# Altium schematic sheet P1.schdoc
size 594 x 419 mm; Symbol: Drawing-Symbol_A4; Company: 嘉立创EDA; Version: V1.0; Page Size: A4; @Project Name: 2026-07-10_18-27-02-有刷私服2; @Update Date: 2026-07-10; @Create Date: 2026-07-10; Device: Drawing-Symbol_A4; @Board Name: Board1; @Page Name: P1; @Create Time: 18:27:26; @Page Count: 1; @Page No: 1; @Schematic Name: Schematic1; @Update Time: 18:27:26; @Assembly Variant: Basic; Border: 1; Title Block Position: 3; Size: A4; Width: 2338; Height: 1652; Region Start: 1; X Region Count: 6; Y Region Count: 4; Blade Width: 10
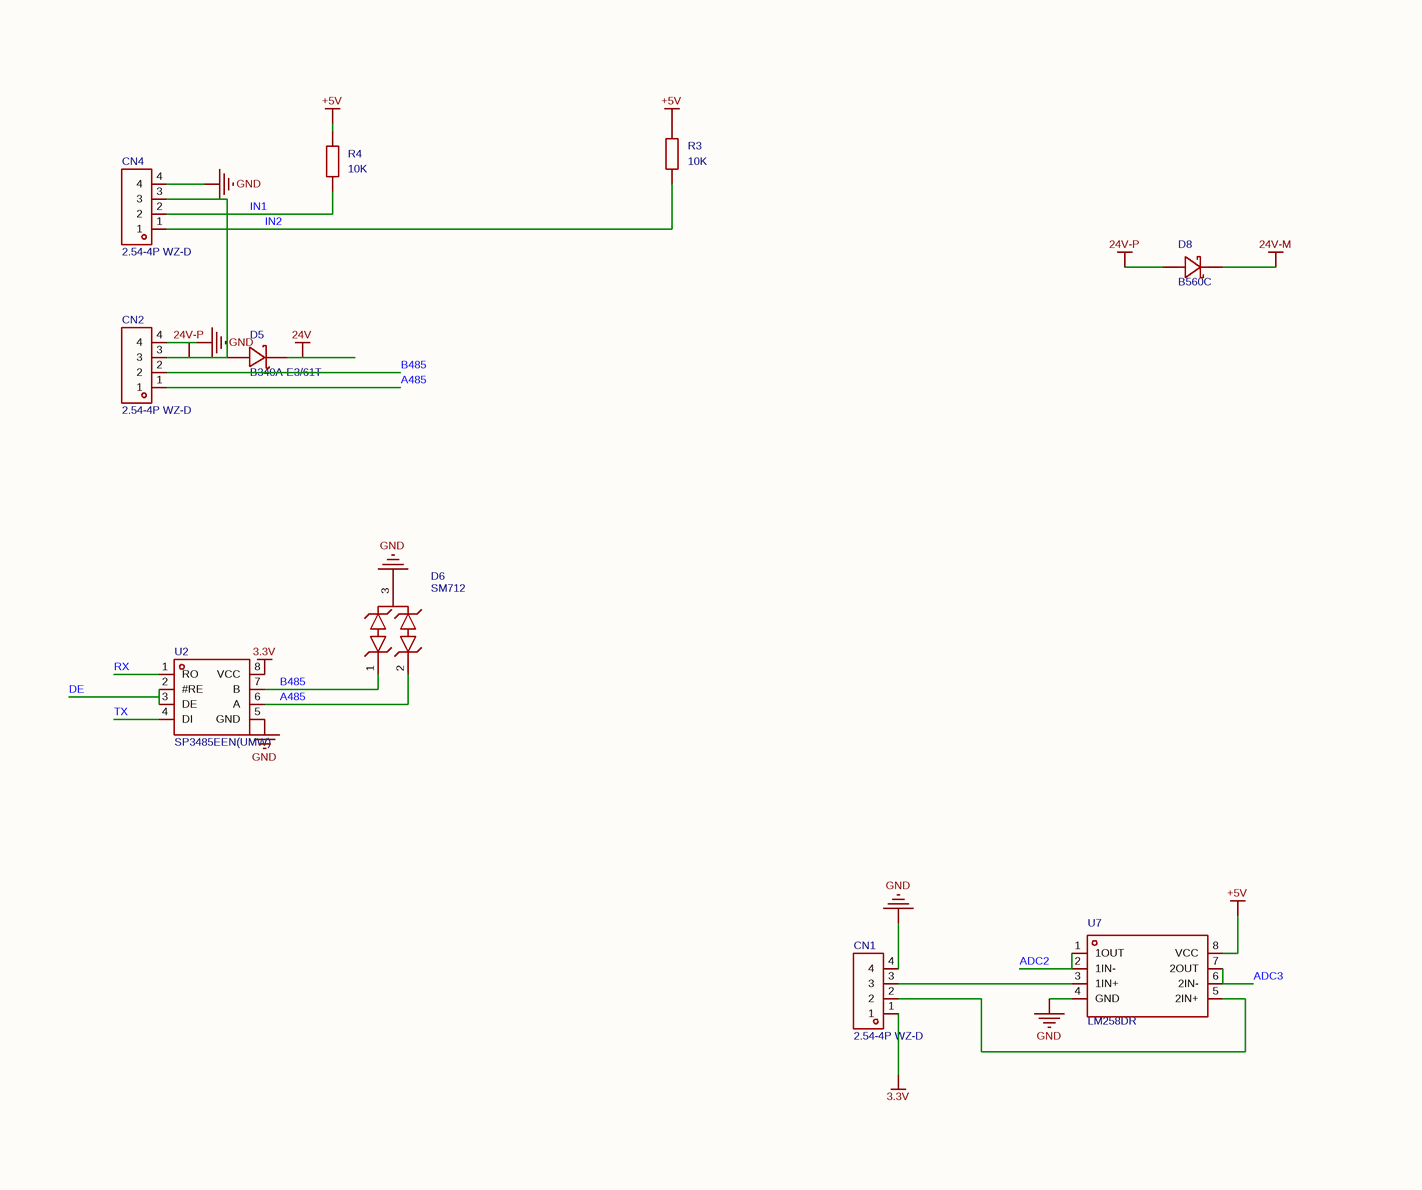
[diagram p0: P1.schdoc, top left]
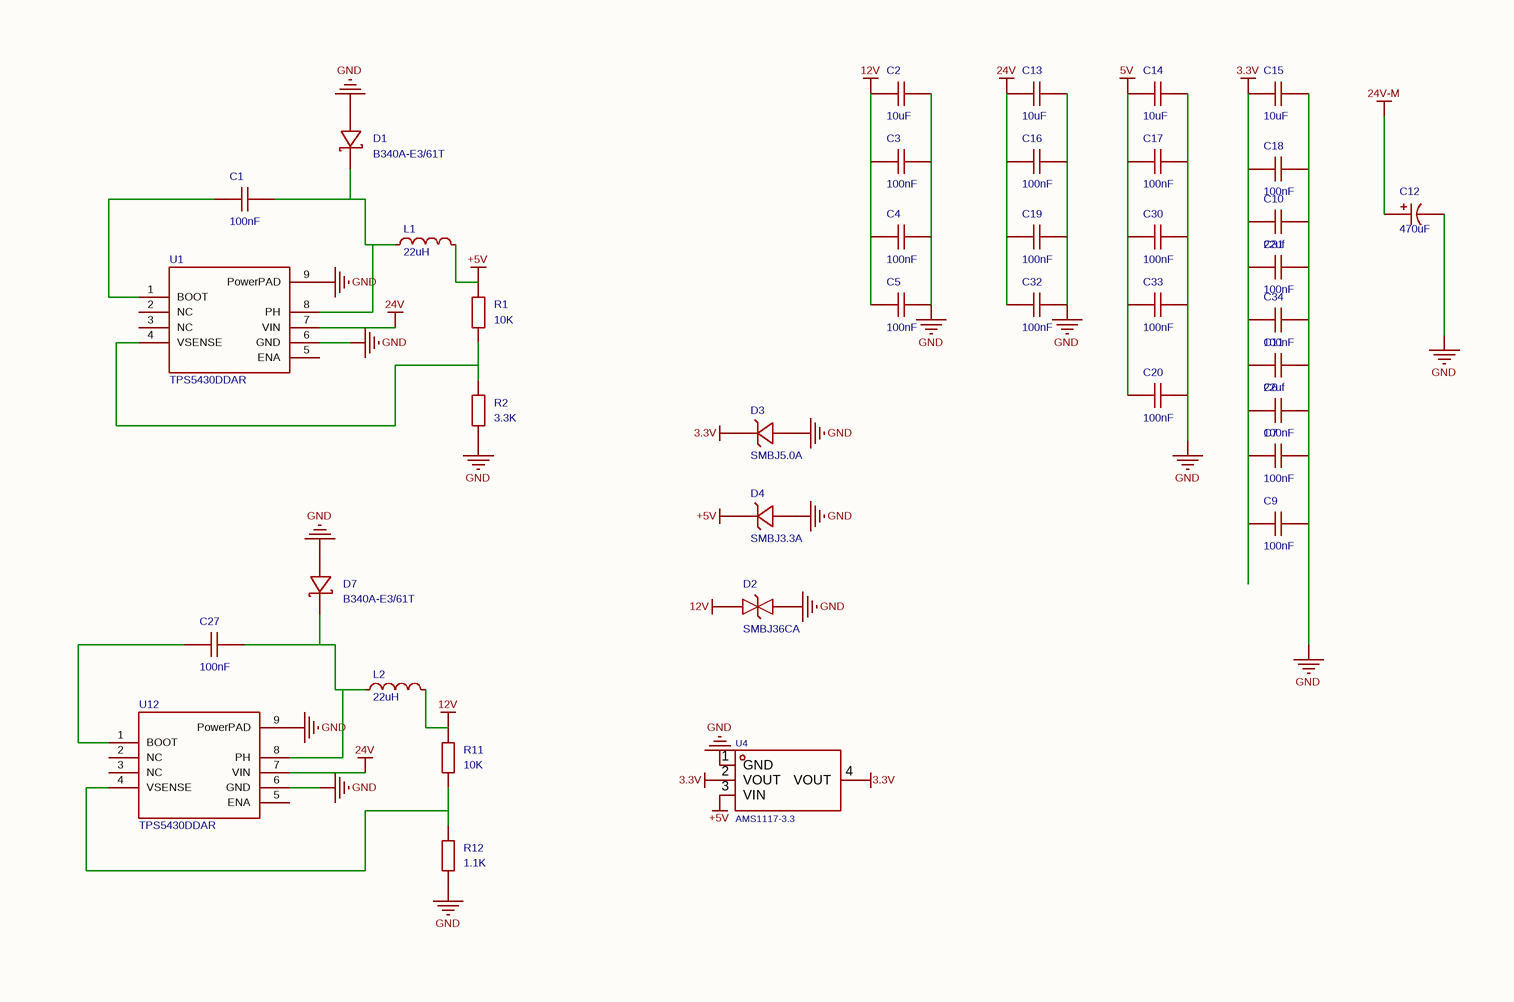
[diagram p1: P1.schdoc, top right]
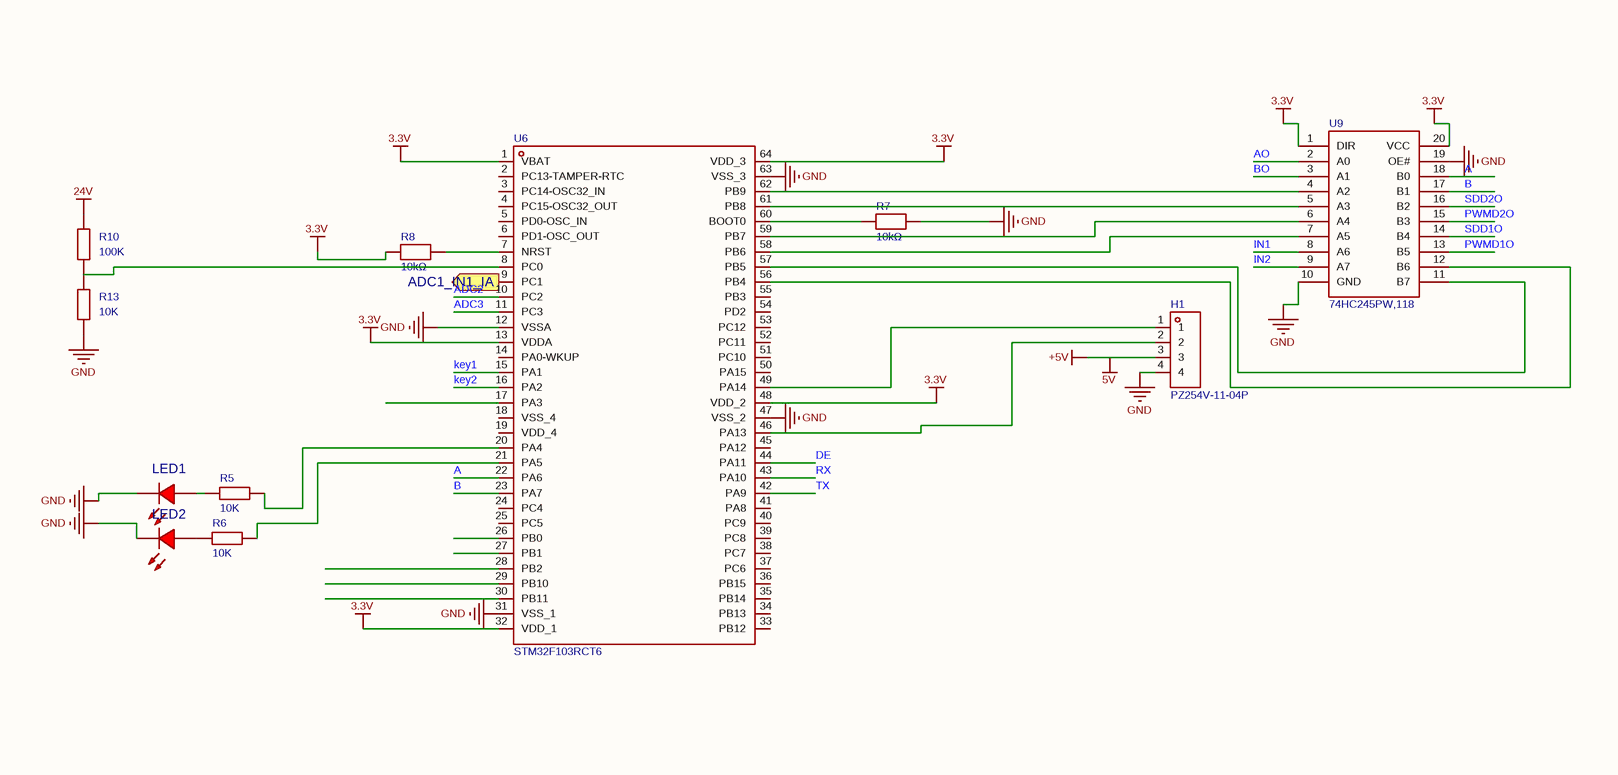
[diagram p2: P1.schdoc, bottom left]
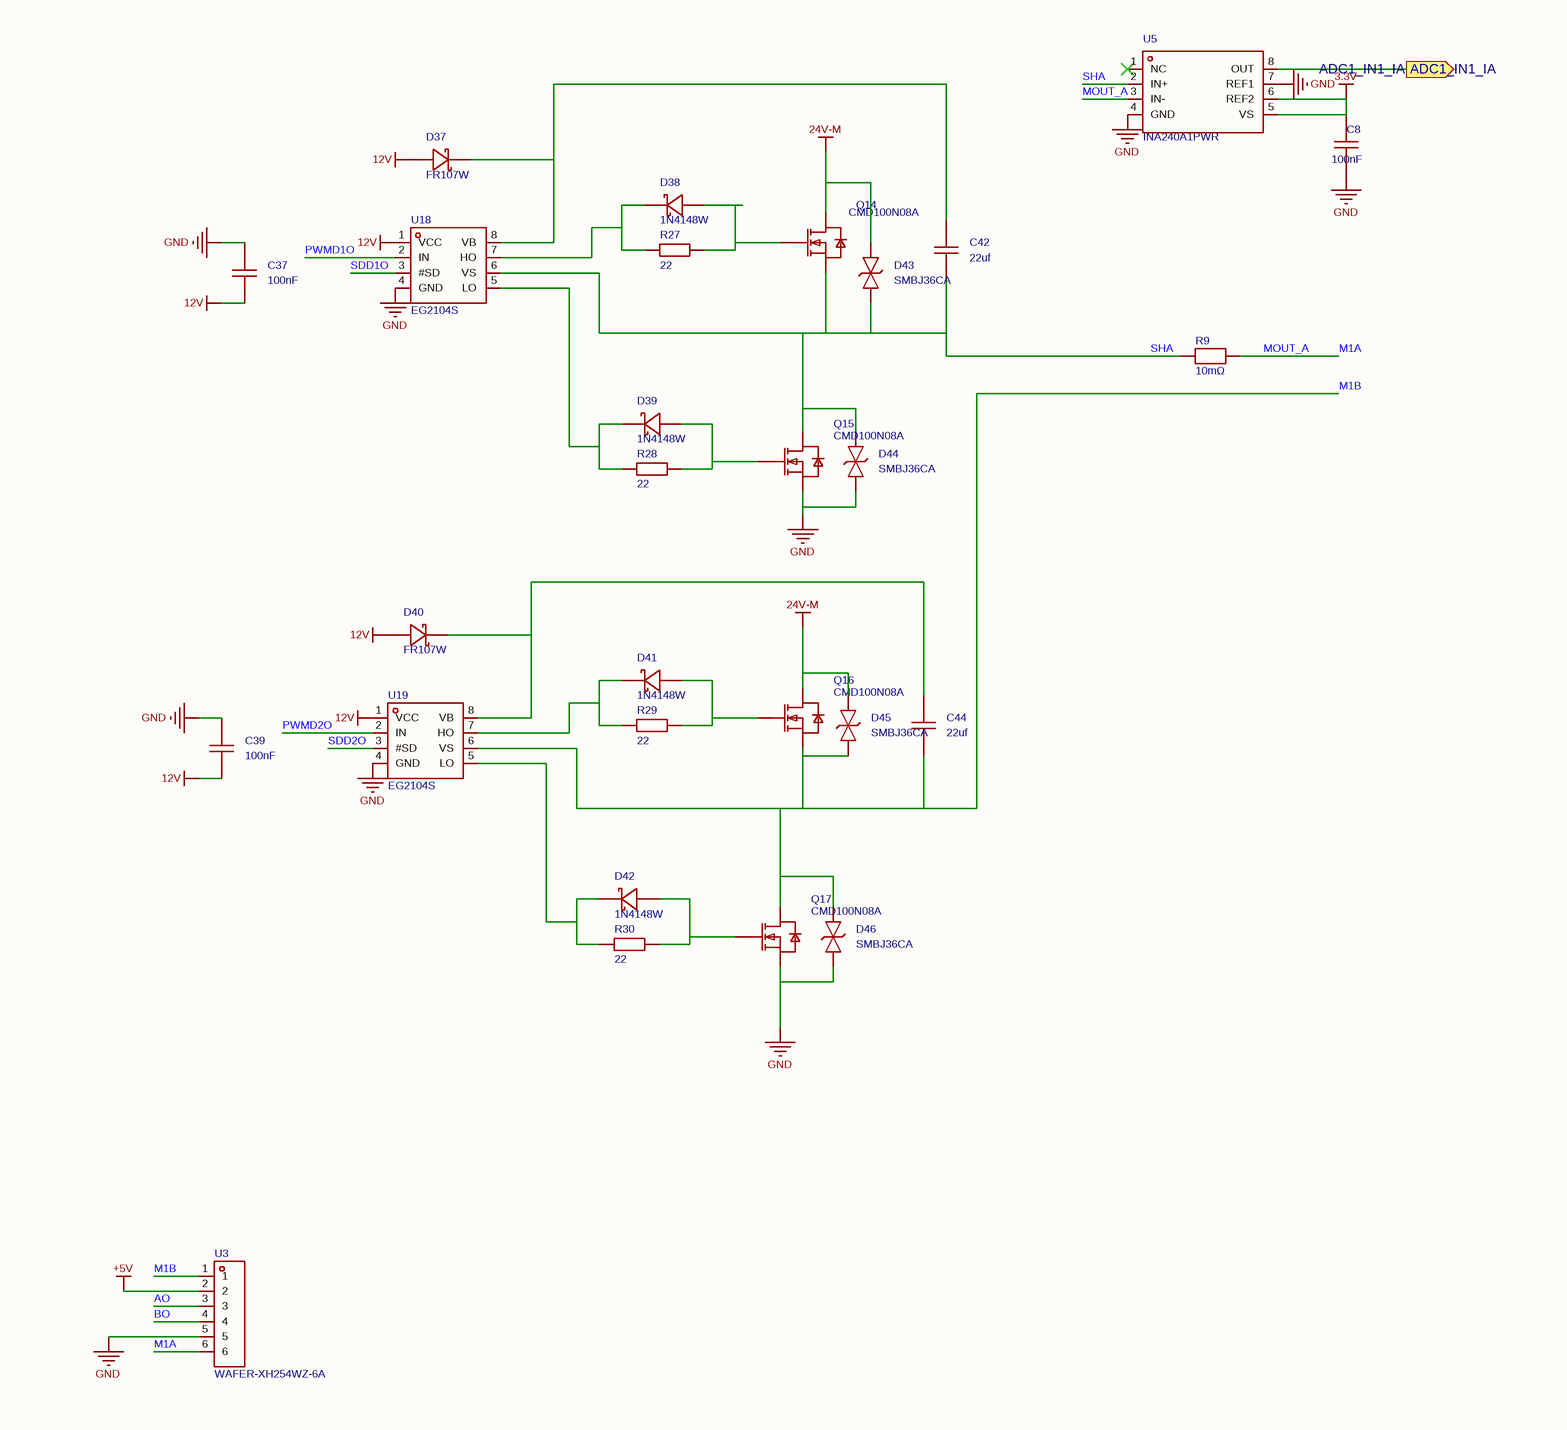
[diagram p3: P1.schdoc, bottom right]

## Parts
C1  100nF  [C0603]
C2  10uF  [C1210]
C3  100nF  [C0603]
C4  100nF  [C0603]
C5  100nF  [C0603]
C6  100nF  [C0603]
C7  100nF  [C0603]
C8  100nF  [C0603]
C9  100nF  [C0603]
C10  22uf  [C1210]
C11  22uf  [C1210]
C12  470uF  [CAP-TH_BD10.0-P5.00-D0.6-FD]
C13  10uF  [C1210]
C14  10uF  [C1210]
C15  10uF  [C1210]
C16  100nF  [C0603]
C17  100nF  [C0603]
C18  100nF  [C0603]
C19  100nF  [C0603]
C20  100nF  [C0603]
C27  100nF  [C0603]
C30  100nF  [C0603]
C31  100nF  [C0603]
C32  100nF  [C0603]
C33  100nF  [C0603]
C34  100nF  [C0603]
C37  100nF  [C0603]
C39  100nF  [C0603]
C42  22uf  [C1210]
C44  22uf  [C1210]
CN1  2.54-4P WZ-D  [CONN-TH_2.54-4P-WZ-D]
CN2  2.54-4P WZ-D  [CONN-TH_2.54-4P-WZ-D]
CN4  2.54-4P WZ-D  [CONN-TH_2.54-4P-WZ-D]
D1  B340A-E3/61T  [SMA_L4.3-W2.6-LS5.2-RD]
D2  SMBJ36CA  [SMB_L4.6-W3.6-LS5.4-BI]
D3  SMBJ5.0A  [SMB_L4.6-W3.6-LS5.4-RD]
D4  SMBJ3.3A  [SMB_L4.6-W3.6-LS5.4-RD]
D5  B340A-E3/61T  [SMA_L4.3-W2.6-LS5.2-RD]
D6  SM712  [SOT-23-3_L2.9-W1.3-P1.90-LS2.4-BR]
D7  B340A-E3/61T  [SMA_L4.3-W2.6-LS5.2-RD]
D8  B560C  [SMC_L6.9-W5.9-LS7.9-RD]
D37  FR107W  [SOD-123FL_L2.7-W1.8-LS3.8-RD]
D38  1N4148W  [SOD-123_L2.7-W1.6-LS3.7-FD]
D39  1N4148W  [SOD-123_L2.7-W1.6-LS3.7-FD]
D40  FR107W  [SOD-123FL_L2.7-W1.8-LS3.8-RD]
D41  1N4148W  [SOD-123_L2.7-W1.6-LS3.7-FD]
D42  1N4148W  [SOD-123_L2.7-W1.6-LS3.7-FD]
D43  SMBJ36CA  [SMB_L4.6-W3.6-LS5.4-BI]
D44  SMBJ36CA  [SMB_L4.6-W3.6-LS5.4-BI]
D45  SMBJ36CA  [SMB_L4.6-W3.6-LS5.4-BI]
D46  SMBJ36CA  [SMB_L4.6-W3.6-LS5.4-BI]
H1  PZ254V-11-04P  [HDR-TH_4P-P2.54-V-M]
L1  22uH  [IND-SMD_L7.0-W6.6_FXL0630]
L2  22uH  [IND-SMD_L7.0-W6.6_FXL0630]
LED1  (no value)  [LED_0603]
LED2  (no value)  [LED_0603]
Q14  CMD100N08A  [TO-252-3_L6.5-W5.8-P4.58-LS9.5-BR]
Q15  CMD100N08A  [TO-252-3_L6.5-W5.8-P4.58-LS9.5-BR]
Q16  CMD100N08A  [TO-252-3_L6.5-W5.8-P4.58-LS9.5-BR]
Q17  CMD100N08A  [TO-252-3_L6.5-W5.8-P4.58-LS9.5-BR]
R1  10K  [R0603]
R2  3.3K  [R0603]
R3  10K  [R0603]
R4  10K  [R0603]
R5  10K  [R0603]
R6  10K  [R0603]
R7  10kΩ  [R0603]
R8  10kΩ  [R0603]
R9  10mΩ  [R1206]
R10  100K  [R0603]
R11  10K  [R0603]
R12  1.1K  [R0603]
R13  10K  [R0603]
R27  22  [R0603]
R28  22  [R0603]
R29  22  [R0603]
R30  22  [R0603]
U1  TPS5430DDAR  [ESOP-8_L4.9-W3.9-P1.27-LS6.0-TL-EP]
U2  SP3485EEN(UMW)  [SOP-8_L5.0-W4.0-P1.27-LS6.0-BL]
U3  WAFER-XH254WZ-6A  [CONN-TH_6P-P2.50_WAFER-XH254WZ-6A]
U4  AMS1117-3.3  [SOT-223-3_L6.5-W3.4-P2.30-LS7.0-BR]
U5  INA240A1PWR  [TSSOP-8_L4.4-W3.0-P0.65-LS6.4-BL]
U6  STM32F103RCT6  [LQFP-64_L10.0-W10.0-P0.50-LS12.0-BL]
U7  LM258DR  [SOIC-8_L5.0-W4.0-P1.27-LS6.0-BL]
U9  74HC245PW,118  [TSSOP-20_L6.5-W4.4-P0.65-LS6.4-BL]
U12  TPS5430DDAR  [ESOP-8_L4.9-W3.9-P1.27-LS6.0-TL-EP]
U18  EG2104S  [SOIC-8_L5.0-W4.0-P1.27-LS6.0-BL]
U19  EG2104S  [SOIC-8_L5.0-W4.0-P1.27-LS6.0-BL]

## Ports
ADC1_IN1_IA (out)

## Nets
3.3V: C6.1 C7.1 C8.2 C9.1 C10.1 C11.1 C15.1 C18.1 C31.1 C34.1 CN1.1 D3.1(K) R8.1 U2.8(VCC) U4.2(VOUT) U4.4(VOUT) U5.5(VS) U5.6(REF2) U6.1(VBAT) U6.13(VDDA) U6.32(VDD_1) U6.48(VDD_2) U6.64(VDD_3) U9.1(DIR) U9.20(VCC)
12V: C2.1 C3.1 C4.1 C5.1 C37.2 C39.2 D2.1 D37.2(A) D40.2(A) L2.2 R11.2 U18.1(VCC) U19.1(VCC)
24V: C13.1 C16.1 C19.1 C32.1 D5.1(K) R10.2 U1.7(VIN) U12.7(VIN)
24V-M: C12.1 D8.1(K) D43.2 D45.2 Q14.2(D) Q16.2(D)
24V-P: CN2.3 CN4.3 D5.2(A) D8.2(A)
+5V: C14.1 C17.1 C20.1 C30.1 C33.1 D4.1(K) H1.3 L1.2 R1.2 R3.2 R4.2 U3.2 U4.3(VIN) U7.8(VCC)  [also labelled 5V]
GND: C2.2 C3.2 C4.2 C5.2 C6.2 C7.2 C8.1 C9.2 C10.2 C11.2 C12.2 C13.2 C14.2 C15.2 C16.2 C17.2 C18.2 C19.2 C20.2 C30.2 C31.2 C32.2 C33.2 C34.2 C37.1 C39.1 CN1.4 CN2.4 CN4.4 D1.2(A) D2.2 D3.2(A) D4.2(A) D6.3 D7.2(A) D44.1 D46.1 H1.4 LED1.1(C) LED2.1(C) Q15.3(S) Q17.3(S) R2.1 R7.2 R12.1 R13.1 U1.6(GND) U1.9(PowerPAD) U2.5(GND) U3.5 U4.1(GND) U5.4(GND) U5.7(REF1) U6.12(VSSA) U6.31(VSS_1) U6.47(VSS_2) U6.63(VSS_3) U7.4(GND) U9.10(GND) U9.19(OE#) U12.6(GND) U12.9(PowerPAD) U18.4(GND) U19.4(GND)
A: U6.22(PA6) U9.18(B0)
A485: CN2.1 D6.2 U2.6(A)
ADC1_IN1_IA: U5.8(OUT) U6.9(PC1) ; port ADC1_IN1_IA
ADC2: U6.10(PC2) U7.1(1OUT) U7.2(1IN-)
ADC3: U6.11(PC3) U7.6(2IN-) U7.7(2OUT)
AO: U3.3 U9.2(A0)
B: U6.23(PA7) U9.17(B1)
B485: CN2.2 D6.1 U2.7(B)
BO: U3.4 U9.3(A1)
DE: U2.2(#RE) U2.3(DE) U6.44(PA11)
IN1: CN4.2 R4.1 U9.8(A6)
IN2: CN4.1 R3.1 U9.9(A7)
key1: U6.15(PA1)
key2: U6.16(PA2)
M1A: R9.1 U3.6 U5.3(IN-)  [also labelled MOUT_A]
M1B: C44.1 D45.1 D46.2 Q16.3(S) Q17.2(D) U3.1 U19.6(VS)
PWMD1O: U9.13(B5) U18.2(IN)
PWMD2O: U9.15(B3) U19.2(IN)
RX: U2.1(RO) U6.43(PA10)
SDD1O: U9.14(B4) U18.3(#SD)
SDD2O: U9.16(B2) U19.3(#SD)
SHA: C42.1 D43.1 D44.2 Q14.3(S) Q15.2(D) R9.2 U5.2(IN+) U18.6(VS)
TX: U2.4(DI) U6.42(PA9)
NetC1_1: C1.1 U1.1(BOOT)
NetC1_2: C1.2 D1.1(K) L1.1 U1.8(PH)
NetC27_1: C27.1 U12.1(BOOT)
NetC27_2: C27.2 D7.1(K) L2.1 U12.8(PH)
NetC42_2: C42.2 D37.1(K) U18.8(VB)
NetC44_2: C44.2 D40.1(K) U19.8(VB)
NetCN1_2: CN1.2 U7.5(2IN+)
NetCN1_3: CN1.3 U7.3(1IN+)
NetD38_1: D38.1(A) Q14.1(G) R27.2
NetD38_2: D38.2(K) R27.1 U18.7(HO)
NetD39_1: D39.1(A) Q15.1(G) R28.2
NetD39_2: D39.2(K) R28.1 U18.5(LO)
NetD41_1: D41.1(A) Q16.1(G) R29.2
NetD41_2: D41.2(K) R29.1 U19.7(HO)
NetD42_1: D42.1(A) Q17.1(G) R30.2
NetD42_2: D42.2(K) R30.1 U19.5(LO)
NetH1_1: H1.1 U6.49(PA14)
NetH1_2: H1.2 U6.46(PA13)
NetLED1_2: LED1.2(A) R5.1
NetLED2_2: LED2.2(A) R6.1
NetR1_1: R1.1 R2.2 U1.4(VSENSE)
NetR5_2: R5.2 U6.20(PA4)
NetR6_2: R6.2 U6.21(PA5)
NetR7_1: R7.1 U6.60(BOOT0)
NetR8_2: R8.2 U6.7(NRST)
NetR10_1: R10.1 R13.2 U6.8(PC0)
NetR11_1: R11.1 R12.2 U12.4(VSENSE)
NetU6_56: U6.56(PB4) U9.12(B6)
NetU6_57: U6.57(PB5) U9.11(B7)
NetU6_58: U6.58(PB6) U9.7(A5)
NetU6_59: U6.59(PB7) U9.6(A4)
NetU6_61: U6.61(PB8) U9.5(A3)
NetU6_62: U6.62(PB9) U9.4(A2)

Not connected (* = marked no-connect by the designer): U1 2(NC) 3(NC) 5(ENA); U5 1(NC)*; U6 2(PC13-TAMPER-RTC) 3(PC14-OSC32_IN) 4(PC15-OSC32_OUT) 5(PD0-OSC_IN) 6(PD1-OSC_OUT) 14(PA0-WKUP) 17(PA3) 18(VSS_4) 19(VDD_4) 24(PC4) 25(PC5) 26(PB0) 27(PB1) 28(PB2) 29(PB10) 30(PB11) 33(PB12) 34(PB13) 35(PB14) 36(PB15) 37(PC6) 38(PC7) 39(PC8) 40(PC9) 41(PA8) 45(PA12) 50(PA15) 51(PC10) 52(PC11) 53(PC12) 54(PD2) 55(PB3); U12 2(NC) 3(NC) 5(ENA)

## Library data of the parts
C1 C27 C37 C39 = CAP_0603: Symbol: Capacitance; 3D Model: ac125912035d415993ca9572d50418b10819f05c4eef4c71ace90d822a990e87; 3D Model Transform: 62.992,31.496,0,0,0,0,0,0,0; ConvertToPcb: yes; ModelName: C0603_L1.6-W0.8-H0.8
C2 C10 C11 C13-C15 C42 C44 = GRM32EC72A106KE05L: 容值:10uF;精度:±10%;额定电压:100V;温度系数:X7S;; Manufacturer: muRata(村田); 3D Model: 833068e7fe044595a6eec77c561794550819f05c4eef4c71ace90d822a990e87; 3D Model Transform: 125.984,98.425,0,0,0,0,0,0,0; Tolerance: ±10%; Voltage Rating: 100V; Temperature Coefficient: X7S; AddInBom: yes; ModelName: C1210_L3.2-W2.5-H2.5
C3-C7 C9 C16-C20 C30-C34 = CL10B104KB8NNNC: 容值:100nF;精度:±10%;额定电压:50V;温度系数:X7R;; Manufacturer: SAMSUNG(三星); 3D Model: ac125912035d415993ca9572d50418b10819f05c4eef4c71ace90d822a990e87; 3D Model Transform: 62.992,31.496,0,0,0,0,0,0,0; Tolerance: ±10%; Voltage Rating: 50V; Temperature Coefficient: X7R; AddInBom: yes; ModelName: C0603_L1.6-W0.8-H0.8
C8 = CGA0603X7R104K500JT: 容值:100nF;精度:±10%;额定电压:50V;温度系数:X7R;; Manufacturer: HRE(芯声); Add into BOM: yes; 3D Model: ac125912035d415993ca9572d50418b1; 3D Model Transform: 62.992,31.496,0,0,0,0,0,0,0; Channel ID: $1I59094; Tolerance: ±10%; Voltage Rating: 50V; Temperature Coefficient: X7R; PCB Layer: TopLayer; ModelName: C0603_L1.6-W0.8-H0.8
C12 = ERG35V470M10X13: 容值:470uF;精度:±20%;额定电压:35V;纹波电流:1.23A@100kHz;等效串联电阻(ESR):46mΩ@100kHz;; Manufacturer: JIERR(捷而瑞); AddInBom: yes; ModelId: e69a8877034041adb17289105fbfdf3e0819f05c4eef4c71ace90d822a990e87; ModelTransform: 394.094,393.211,0,0,0,0,-0.005,0,-137.795; Tolerance: ±20%; Voltage Rating: 35V; Pin Spacing: 5mm; Lifetime: 2000hrs@105℃
CN1 CN2 CN4 = 2.54-4P WZ-D: 插针结构:1x4P;间距:2.54mm;安装方式:弯插;参考系列:XH;总PIN数:4P;排数:1;每排PIN数:4;额定电流:3A;触头材质:锡青磷铜;触头镀层:锡;工作温度:-25℃~+85℃;; Manufacturer: SHOU HAN(首韩); 3D Model: 1499c3a97616414584af1c8130909a380819f05c4eef4c71ace90d822a990e87; 3D Model Transform: 492.5187,433.07,0,0,0,0,-0.005,-59.641,-133.858; Pins Structure: 1x4P; Pitch: 2.54mm; Reference Series: XH; Number of PINs Per Row: 4; Current Rating: 3A; Voltage Rating: 250V; Plastic Material: PA66; AddInBom: yes
D1 D5 D7 = B340A-E3/61T: 正向压降(Vf):550mV@3A;直流反向耐压(Vr):40V;整流电流:3A;; Manufacturer: VISHAY(威世); 3D Model: e3551acb3c5a4975a5e9d36087fe1fa20819f05c4eef4c71ace90d822a990e87; 3D Model Transform: 185.039,102.362,0,0,0,0,0,0,0; Voltage - DC Reverse(Vr): 40V; Current - Rectified: 3A; Reverse Leakage Current (Ir): 500uA@40V; Operating Junction Temperature Range: -65℃~+150℃; Non-Repetitive Peak Forward Surge Current: 65A; AddInBom: yes
D2 D43-D46 = SMBJ36CA_C19077589: 极性:双向;反向截止电压(Vrwm):36V;钳位电压:58.1V;峰值脉冲电流(Ipp):10.33A@10/1000us;峰值脉冲功率(Ppp):600W@10/1000us;击穿电压:44.2V;; Manufacturer: R+O(宏嘉诚); 3D Model: 56a671846d664f15ac0751d5510bb56a0819f05c4eef4c71ace90d822a990e87; 3D Model Transform: 212.598,142.5194,0,0,0,0,0,0,0; Polarity: 双向; Reverse Stand-Off Voltage (Vrwm): 36V; Clamping Voltage: 58.1V; Voltage - Breakdown: 44.2V; Reverse Leakage Current (Ir): 5uA; Number of Channels: 单路; level of protection: IEC 61000-4-2; Type: TVS; AddInBom: yes
D3 D4 = SMBJ5.0A_C19077558: 极性:单向;反向截止电压(Vrwm):5V;钳位电压:9.2V;峰值脉冲电流(Ipp):65.22A@10/1000us;峰值脉冲功率(Ppp):600W@10/1000us;击穿电压:7V;; Manufacturer: R+O(宏嘉诚); 3D Model: 4a07d3f25b7245848b9fc4bc88d0221f0819f05c4eef4c71ace90d822a990e87; 3D Model Transform: 212.598,142.5194,0,0,0,0,0,0,0; Polarity: 单向; Reverse Stand-Off Voltage (Vrwm): 5V; Clamping Voltage: 9.2V; Voltage - Breakdown: 7V; Reverse Leakage Current (Ir): 800uA; Number of Channels: 单路; level of protection: IEC 61000-4-2; Type: TVS; AddInBom: yes
D6 = SM712_C7420375: 极性:双向;反向截止电压(Vrwm):12V；7V;钳位电压:16V；26V;峰值脉冲电流(Ipp):12A;峰值脉冲功率(Ppp):300W;击穿电压:7.5V；13.5V;; Manufacturer: R+O(宏嘉诚); AddInBom: yes; ModelId: c62791f0466c4ae2a892c056b845b0ca0819f05c4eef4c71ace90d822a990e87; ModelName: SOT-23-3P_L2.9-W1.3-H1.0-LS2.4-P0.95; ModelTransform: 98.425,114.173,0,180,0,0,0.0005,-0.0005,0; Polarity: 双向; Reverse Stand-Off Voltage (Vrwm): 12V；7V; Peak Pulse Current (Ipp): 12A; Peak Pulse Power Dissipation (Ppp): 300W; Reverse Leakage Current (Ir): 1uA；2uA; Number of Channels: 双路; level of protection: IEC 61000-4-5；IEC 61000-4-2; Type: ESD; Junction Capacitance: 75pF
D8 = B560C_C6807784: 二极管配置:独立式;正向压降(Vf):700mV@5A;直流反向耐压(Vr):60V;整流电流:5A;; Manufacturer: FUXINSEMI(富芯森美); 3D Model: 181deed3e51b4528a83dd624c23bafda0819f05c4eef4c71ace90d822a990e87; 3D Model Transform: 314.96,236.22,0,0,0,0,0,0,0; Diode Configuration: 独立式; Voltage - DC Reverse(Vr): 60V; Current - Rectified: 5A; Reverse Leakage Current (Ir): 100uA@60V; Operating Junction Temperature Range: -55℃~+150℃; AddInBom: yes
D37 D40 = FR107W_C18199114: 二极管配置:1个独立式;正向压降(Vf):1.3V@1A;直流反向耐压(Vr):1kV;整流电流:1A;反向恢复时间(Trr):500ns;; Manufacturer: R+O(宏嘉诚); 3D Model: 86f9151e155e4fe2af0c4f2e0a80302e0819f05c4eef4c71ace90d822a990e87; 3D Model Transform: 141.732,70.866,0,180,0,0,0,0,0; Diode Configuration: 1个独立式; Voltage - DC Reverse(Vr): 1kV; Current - Rectified: 1A; Reverse Leakage Current (Ir): 2uA@1000V; Reverse Recovery Time (trr): 500ns; Operating Junction Temperature Range: -55℃~+150℃; Non-Repetitive Peak Forward Surge Current: 30A; AddInBom: yes; ModelName: SOD-123FL_L2.8-W1.8-H1.1-LS3.6
D38 D39 D41 D42 = 1N4148W_C7420318: 二极管配置:独立式;整流电流:150mA;直流反向耐压(Vr):100V;正向压降(Vf):1.25V@150mA;反向恢复时间(Trr):4ns;; Manufacturer: R+O(宏嘉诚); 3D Model: 5054d9b7be8b429dad093a54b517b4dd0819f05c4eef4c71ace90d822a990e87; 3D Model Transform: 145.669,61.024,0,0,0,0,0,0,0; Diode Configuration: 独立式; Pd - Power Dissipation: 400mW; Current - Rectified: 150mA; Voltage - DC Reverse(Vr): 100V; Non-Repetitive Peak Forward Surge Current: 2A; Reverse Leakage Current (Ir): 1uA@75V; Reverse Recovery Time (trr): 4ns; Operating Junction Temperature Range: -55℃~+150℃; AddInBom: yes
H1 = PZ254V-11-04P: 插针结构:1x4P;间距:2.54mm;行距:-;圆针/方针:方针;安装方式:直插;排数:单排;总PIN位数:4P;额定电流:3A;额定电压:250V;配合针长度:6mm;塑高:2.5mm;端接针长度:3mm;触头材质:-;工作温度:-40℃~+105℃;颜色:黑色;; Manufacturer: XFCN(兴飞); Symbol: PZ254V-11-04P_C2691448; 3D Model: 112f4d05e8d64e99ab9a333894bea4f90819f05c4eef4c71ace90d822a990e87; 3D Model Transform: 399.999,104.7242,0,0,0,0,0,0,-118.11; Pin Structure: 1x4P; Pitch: 2.54mm; Circluar Pins/Square Pins: 方针; Current Rating: 3A; Voltage Rating (Max): 250V; AddInBom: yes; ModelName: HDR-TH_4P-P2.54-M-LI-1X4P
L1 L2 = FXL0630-220-M: 电感值:22uH;精度:±20%;额定电流:2.5A;饱和电流(Isat):3A;类型:一体成型电感;; Manufacturer: cjiang(长江微电); 3D Model: 6712504104d74f0ca01cd7d0df9965b70819f05c4eef4c71ace90d822a990e87; 3D Model Transform: 275.59,259.842,0,0,0,0,0,0,0; Tolerance: ±20%; Current Rating: 2.5A; Current - Saturation(Isat): 3A; DC Resistance(DCR): 200mΩ; Type: 一体成型电感; AddInBom: yes; ModelName: IND-SMD_L7.0-W6.6-H2.8_FXL0630
LED1 LED2 = LED_0603-R: Symbol: LED_R; Convert to PCB: yes; 3D Model: dd8257b0d61a4cd7b68939a056e080950819f05c4eef4c71ace90d822a990e87; 3D Model Transform: 58.72,29.4,22.03,0,0,0,0,0,0; ModelName: LED-0603_R
Q14-Q17 = CMD100N08A: 数量:1个N沟道;漏源电压(Vdss):80V;连续漏极电流(Id):100A;导通电阻(RDS(on)):6mΩ@10V;耗散功率(Pd):100W;阈值电压(Vgs(th)):2V;; Manufacturer: Cmos(广东场效应半导体); 3D Model: e13559c25c304a648cbd5c84b311c7470819f05c4eef4c71ace90d822a990e87; 3D Model Transform: 374.015,256.299,0,0,0,0,-29.41,0,0; Number: 1个N沟道; Drain to Source Voltage: 80V; Current - Continuous Drain(Id): 100A; Pd - Power Dissipation: 100W; Gate Threshold Voltage (Vgs(th)): 2V; Gate Charge(Qg): 120nC; Input Capacitance(Ciss): 4nF; Reverse Transfer Capacitance (Crss@Vds): 365pF; AddInBom: yes
R1-R6 R10-R13 R27-R30 = Res_0603: Symbol: 电阻; 3D Model: fc143cca1e79419f9cd78b61e9279f080819f05c4eef4c71ace90d822a990e87; 3D Model Transform: 31.8897,63.7794,0,90,0,0,0,0,0; ConvertToPcb: yes
R7 R8 = FRC0603J103 TS: 电阻类型:厚膜电阻;阻值:10kΩ;精度:±5%;功率:100mW;工作电压:75V;温度系数:±100ppm/℃;; Manufacturer: FOJAN(富捷); 3D Model: fc143cca1e79419f9cd78b61e9279f080819f05c4eef4c71ace90d822a990e87; 3D Model Transform: 31.8897,63.7794,0,90,0,0,0,0,0; Tolerance: ±5%; Power(Watts): 100mW; Voltage-Supply(Max): 75V; AddInBom: yes
R9 = RE1206F1R010: 电阻类型:采样电阻；合金电阻;阻值:10mΩ;精度:±1%;功率:1W;温度系数:±50ppm/℃;; Manufacturer: JIERR(捷而瑞); Add into BOM: yes; 3D Model: 89a1f13db2384da588040e0b3c55bf66; 3D Model Transform: 125.984,62.992,0,0,0,0,0,0,0; Tolerance: ±1%; Power(Watts): 1W; ModelName: R1206_L3.2-W1.6-H0.6
U1 U12 = TPS5430DDAR: 功能类型:降压型;工作电压:5.5V~36V;输出电压:1.221V~32.04V;输出电流:3A;输出类型:可调;; Manufacturer: TI(德州仪器); 3D Model: 821ddb58f3244ffb9a5d6f8174c5b14e0819f05c4eef4c71ace90d822a990e87; 3D Model Transform: 236.22,192.913,0,0,0,0,0,0,0; Function: 降压型; Output Current: 3A; Frequency - Switching: 500kHz; Synchronous Rectifier: 否; Number of Outputs: 1; Topology: 降压式; Quiescent Current: 4.4mA; Switch tube (built-in/external): 内置; Output Type: 可调; AddInBom: yes
U2 = SP3485EEN(UMW): 类型:收发器;数据速率:12Mbps;; Manufacturer: UMW(友台半导体); AddInBom: yes; ModelId: a3315c1c78f949e6bb82c6eaca1c53c70819f05c4eef4c71ace90d822a990e87; ModelName: SOP-8_L5.0-W4.0-H1.8-LS6.2-P1.27; ModelTransform: 244.094,196.85,0,90,0,0,0,0,0; Number of Drivers: 1; Voltage - Supply: 2.97V~3.63V; Data Rate: 12Mbps; Number of Nodes: 256; Supply Current (Iq): 520uA; Communication Mode: 半双工
U3 = WAFER-XH254WZ-6A: 插针结构:1x6P;间距:2.54mm;安装方式:弯插;参考系列:XH;总PIN数:6P;排数:1;每排PIN数:6;额定电流:3A;触头材质:黄铜;工作温度:-25℃~+85℃;; Manufacturer: HANBO(汉博); 3D Model: f596b4a523cb447791a74ec300d030630819f05c4eef4c71ace90d822a990e87; 3D Model Transform: 689.36866,300.7868,0,0,0,0,-0.002,-137.795,-133.858; Pins Structure: 1x6P; Pitch: 2.54mm; Reference Series: XH; Number of PINs Per Row: 6; Current Rating: 3A; Voltage Rating: 250V; Plastic Material: PA66; Flame Retardant Rating: UL94V-0; AddInBom: yes
U4 = AMS1117-3.3_C6186: 输出极性:正极;工作电压:15V;输出电压:3.3V;输出电流:1A;电源纹波抑制比(PSRR):72dB@(120Hz);输出类型:固定;; Manufacturer: Advanced Monolithic Systems; 3D Model: 925194bf9823436183a3e0b978a8d0760819f05c4eef4c71ace90d822a990e87; 3D Model Transform: 279.89794,255.905,0,180,0,0,-3.9385,-0.0005,0; Output Configuration: 正极; Voltage - Supply: 15V; Output Voltage: 3.3V; Output Current: 1A; Voltage Dropout: 1.1V@(800mA); standby current: 5mA; Noise: 0.003%Vout; Output Type: 固定; Number of Outputs: 1; AddInBom: yes; ModelName: SOT-223-4P_L6.5-W3.5-H1.6-LS7.0-P2.30
U5 = INA240A1PWR: 放大器数:单路;共模电压:-4V~80V;增益:20V/V;带宽:400kHz;; Manufacturer: TI(德州仪器); 3D Model: 85577802f9634e7e85ffa2fd25a37b6f0819f05c4eef4c71ace90d822a990e87; 3D Model Transform: 118.11,251.968,0,0,0,0,0,0,0; Number of Channels: 单路; Gain: 20V/V; Bandwidth: 400kHz; Ib - Input Bias Current: 90uA; Vos - Input Offset Voltage: 5uV; Differential Voltage: -80V~+80V; Maximum Power Supply Range (Vdd-Vss): 5.5V; Single Supply: 2.7V~5.5V; Quiescent Current: 1.8mA; Input Offset Voltage Drift(Vos TC): 250nV/℃; Slew Rate: 2V/us; Common Mode Rejection Ratio (CMRR): 132dB; Noise density(eN): 40nV/√Hz@1kHz; AddInBom: yes; ModelName: TSSOP-8_L4.4-W3.0-P0.65-LS6.4-BL-2
U6 = STM32F103RCT6: CPU内核:ARM-M3;CPU最大主频:72MHz;应用领域:-;; Manufacturer: ST(意法半导体); 3D Model: cd9de06618c44fcf82654c43a457f83c0819f05c4eef4c71ace90d822a990e87; 3D Model Transform: 472.441,472.441,0,0,0,0,0,0.465,0; CPU Core: ARM-M3; CPU Maximum Speed: 72MHz; Program Storage Size: 256KB; Program Memory Type: FLASH; Number of I/O: 51; ADC (Bit): 12bit; Voltage - Supply: 2V~3.6V; AddInBom: yes; ModelName: LQFP-64_L10.0-W10.0-H1.4-LS12.0-P0.50
U7 = LM258DR: 放大器数:2;轨到轨:-;增益带宽积(GBW):700kHz;输入失调电压(Vos):3mV;压摆率(SR):300V/ms;输入偏置电流(Ib):300nA;; Manufacturer: TI(德州仪器); AddInBom: yes; ModelId: 7abc64c95a1a4a04a4ef38f9097c870b0819f05c4eef4c71ace90d822a990e87; ModelTransform: 192.913,236.22,0,0,0,0,0,0,0; Number of Channels: 2; Maximum Power Supply Range (Vdd-Vss): 32V; Gain Bandwidth Product: 700kHz; Vos - Input Offset Voltage: 3mV; Input Offset Voltage Drift(Vos TC): 7uV/℃; Ib - Input Bias Current: 300nA; Input Offset Current(Ios): 2nA; Input Voltage Noise Density: 40nV/√Hz@1kHz; Common Mode Rejection Ratio(CMRR): 80dB; Input offset current drift(Ios TC): 10pA/℃; Quiescent Current: 700uA; Output Current: 30mA; Single supply: 3V~32V; Dual Supply: 1.5V~16V；-16V~-1.5V
U9 = 74HC245PW,118: 输入类型:-;工作电压:2V~6V;元件数:1;每个元件位数:8;灌电流(IOL):7.8mA;拉电流(IOH):7.8mA;; Manufacturer: Nexperia(安世); 3D Model: c491f68934b34c649df5890a1d97cd0f0819f05c4eef4c71ace90d822a990e87; 3D Model Transform: 251.969,255.906,0,90,0,0,0.0005,0,0; output type: 三态; Voltage - Supply: 2V~6V; Number of Elements: 1; Number of Bits per Element: 8; Channel Type: 双向; Current - Output Low(IOL): 7.8mA; Logic Family: 74HC; Quiescent Current: 160uA; Propagation Delay: 9ns@4.5V,50pF; AddInBom: yes; ModelName: TSSOP-20_L6.5-W4.4-H1.0-LS6.4-P0.65
U18 U19 = EG2104S: 驱动配置:低边；高边;负载类型:MOSFET；IGBT;驱动通道数:-;灌电流(IOL):1.5A;拉电流(IOH):1A;工作电压:10V~20V;上升时间(tr):150ns;下降时间(tf):75ns;; Manufacturer: EG(屹晶微); 3D Model: 7abc64c95a1a4a04a4ef38f9097c870b0819f05c4eef4c71ace90d822a990e87; 3D Model Transform: 192.913,236.22,0,0,0,0,0,0,0; Driven Configuration: 低边；高边; Current - Output Low(IOL): 1.5A; Current - Output High(IOH): 1A; Rise Time: 150ns; Fall Time: 75ns; Input Logic Level - High: 2.5V; Input Logic Level - Low: -300mV~1V; Quiescent Current(Iq): 100uA; AddInBom: yes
